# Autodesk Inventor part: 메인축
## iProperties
Company: 한국ATC센터
Created: 2014-12
Part Number: 메인축
Document SubType Name: Modeling
Designer: KYOUNG IL JANG
Density: 1 g/cm^3
Mass: 27.2374 g
Surface Area: 71.2962 cm^2
Volume: 27.2374 cm^3
Author: KYOUNG IL JANG
